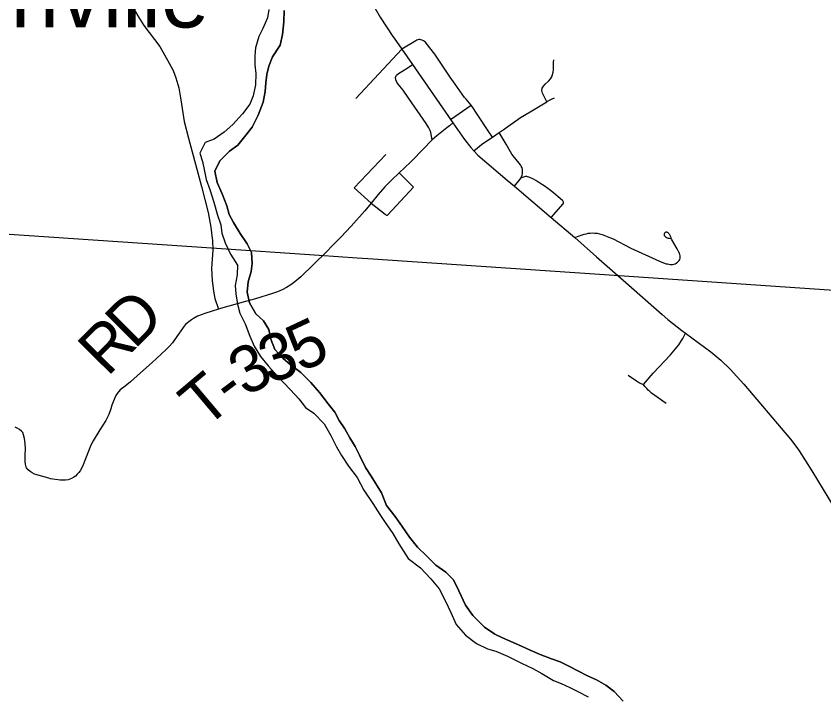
# Model space of a CAD drawing. Extents: x 0 to 34, y 0 to 22.
# Drawn here: x 6.535 to 7.513, y 18.32 to 19.145 of the extents above; entities that cross this region are included whole.
import ezdxf

# ---------------------------------------------------------------- set-up
doc = ezdxf.new("R2010")
doc.units = 0
for name, color, linetype in [('GM_X_County_Road', 7, 'Continuous'), ('GM_X_Major_River', 7, 'Continuous'), ('GM_X_Township_Road', 7, 'Continuous'), ('GM_X_Township_Road_Text', 7, 'Continuous'), ('GM_X_Township_Text', 7, 'Continuous'), ('GM_X_Unincorporated_Text', 7, 'Continuous')]:
    doc.layers.add(name, color=color, linetype=linetype)

msp = doc.modelspace()

# ---------------------------------------------------------------- linework, layer by layer
at = {"layer": 'GM_X_County_Road'}
for points in [[(6.9694, 19.15472), (6.97549, 19.14401), (6.99103, 19.1208), (6.99258, 19.11856), (7.0017, 19.10543), (7.01474, 19.08664), (7.05836, 19.02376), (7.06087, 19.02014), (7.06375, 19.016), (7.07784, 18.99571), (7.08547, 18.98599), (7.0892, 18.98208), (7.09397, 18.97708), (7.12928, 18.94671), (7.13819, 18.93917), (7.18278, 18.90145), (7.21134, 18.87729), (7.23782, 18.85362), (7.24754, 18.84506), (7.27322, 18.82243)], [(7.27322, 18.82243), (7.31724, 18.78362), (7.32407, 18.7776), (7.34126, 18.76436), (7.34544, 18.76127), (7.37628, 18.73848), (7.3883, 18.72855), (7.39951, 18.71769), (7.4162, 18.69918), (7.47264, 18.63286), (7.48028, 18.62268), (7.48321, 18.61849), (7.49872, 18.59416), (7.52584, 18.54883), (7.53463, 18.53611), (7.54442, 18.52416), (7.56365, 18.50395), (7.57609, 18.49101), (7.58953, 18.47705), (7.61443, 18.44873), (7.62015, 18.44201), (7.63038, 18.43057), (7.63847, 18.42135), (7.66073, 18.39596)]]:
    msp.add_lwpolyline(points, dxfattribs=at)
at = {"layer": 'GM_X_Major_River'}
for p, q in [((6.84059, 19.15339), (6.83917, 19.14315)), ((6.85888, 19.1384), (6.85914, 19.15242)), ((6.83917, 19.14315), (6.8336, 19.13059)), ((6.85712, 19.12322), (6.85888, 19.1384)), ((6.8336, 19.13059), (6.82839, 19.12069)), ((6.85459, 19.11032), (6.85712, 19.12322)), ((6.82839, 19.12069), (6.82472, 19.10701)), ((6.82472, 19.10701), (6.82367, 19.09753)), ((6.84525, 19.09621), (6.85459, 19.11032)), ((6.82367, 19.09753), (6.82377, 19.08654)), ((6.84081, 19.0848), (6.84525, 19.09621)), ((6.82377, 19.08654), (6.82499, 19.07594)), ((6.83825, 19.07455), (6.84081, 19.0848)), ((6.82499, 19.07594), (6.82436, 19.06229)), ((6.8372, 19.06468), (6.83825, 19.07455)), ((6.83616, 19.05406), (6.8372, 19.06468)), ((6.82436, 19.06229), (6.82183, 19.04863)), ((6.834, 19.04116), (6.83616, 19.05406)), ((6.82183, 19.04863), (6.81775, 19.03874)), ((6.81775, 19.03874), (6.80877, 19.02691)), ((6.82771, 19.02519), (6.834, 19.04116)), ((6.80877, 19.02691), (6.79716, 19.01392)), ((6.82064, 19.01072), (6.82771, 19.02519)), ((6.79716, 19.01392), (6.78664, 19.00473)), ((6.78664, 19.00473), (6.77461, 18.99628)), ((6.81278, 19.00118), (6.82064, 19.01072)), ((6.77461, 18.99628), (6.76367, 18.99239)), ((6.80305, 18.98896), (6.81278, 19.00118)), ((6.76367, 18.99239), (6.75697, 18.97945)), ((6.7929, 18.98167), (6.80305, 18.98896)), ((6.75697, 18.97945), (6.76047, 18.96925)), ((6.78127, 18.96982), (6.7929, 18.98167)), ((6.76047, 18.96925), (6.76284, 18.95752)), ((6.77532, 18.95764), (6.78127, 18.96982)), ((6.76284, 18.95752), (6.76482, 18.94731)), ((6.77809, 18.94364), (6.77532, 18.95764)), ((6.76482, 18.94731), (6.76909, 18.93522)), ((6.78427, 18.93006), (6.77809, 18.94364)), ((6.76909, 18.93522), (6.77414, 18.91973)), ((6.78969, 18.91533), (6.78427, 18.93006)), ((6.77414, 18.91973), (6.77844, 18.90423)), ((6.79281, 18.90512), (6.78969, 18.91533)), ((6.77844, 18.90423), (6.7827, 18.89253)), ((6.79781, 18.89531), (6.79281, 18.90512)), ((6.7827, 18.89253), (6.78393, 18.88231)), ((6.80587, 18.88213), (6.79781, 18.89531)), ((6.78393, 18.88231), (6.78781, 18.87059)), ((6.81431, 18.86932), (6.80587, 18.88213)), ((6.78781, 18.87059), (6.79436, 18.85701)), ((6.8197, 18.85876), (6.81431, 18.86932)), ((6.82057, 18.8455), (6.8197, 18.85876)), ((6.79436, 18.85701), (6.80281, 18.84345)), ((6.80281, 18.84345), (6.80215, 18.83169)), ((6.81914, 18.83602), (6.82057, 18.8455)), ((6.80215, 18.83169), (6.79999, 18.81879)), ((6.81584, 18.82348), (6.81914, 18.83602)), ((6.79999, 18.81879), (6.80084, 18.80894)), ((6.81444, 18.81096), (6.81584, 18.82348)), ((6.80084, 18.80894), (6.80284, 18.79646)), ((6.8172, 18.79772), (6.81444, 18.81096)), ((6.80284, 18.79646), (6.80558, 18.78549)), ((6.82489, 18.78453), (6.8172, 18.79772)), ((6.80558, 18.78549), (6.81213, 18.77229)), ((6.83442, 18.7759), (6.82489, 18.78453)), ((6.81213, 18.77229), (6.81755, 18.75756)), ((6.84056, 18.76573), (6.83442, 18.7759)), ((6.84293, 18.754), (6.84056, 18.76573)), ((6.81755, 18.75756), (6.82295, 18.74548)), ((6.84797, 18.74116), (6.84293, 18.754)), ((6.82295, 18.74548), (6.83063, 18.73267)), ((6.85752, 18.73064), (6.84797, 18.74116)), ((6.83063, 18.73267), (6.83981, 18.72138)), ((6.86704, 18.72277), (6.85752, 18.73064)), ((6.83981, 18.72138), (6.85127, 18.70898)), ((6.87961, 18.71341), (6.86704, 18.72277)), ((6.89145, 18.70139), (6.87961, 18.71341)), ((6.85127, 18.70898), (6.86693, 18.69245)), ((6.90214, 18.68936), (6.89145, 18.70139)), ((6.86693, 18.69245), (6.87686, 18.68155)), ((6.87686, 18.68155), (6.88528, 18.67102)), ((6.91248, 18.67544), (6.90214, 18.68936)), ((6.92052, 18.66528), (6.91248, 18.67544)), ((6.88528, 18.67102), (6.89517, 18.66429)), ((6.89517, 18.66429), (6.90777, 18.65114)), ((6.9259, 18.65547), (6.92052, 18.66528)), ((6.9328, 18.64531), (6.9259, 18.65547)), ((6.90777, 18.65114), (6.91584, 18.63719)), ((6.93895, 18.63437), (6.9328, 18.64531)), ((6.91584, 18.63719), (6.92277, 18.62324)), ((6.94509, 18.62382), (6.93895, 18.63437)), ((6.92277, 18.62324), (6.92892, 18.61268)), ((6.95048, 18.61326), (6.94509, 18.62382)), ((6.92892, 18.61268), (6.93736, 18.59987)), ((6.9578, 18.59817), (6.95048, 18.61326)), ((6.93736, 18.59987), (6.94769, 18.58633)), ((6.9647, 18.588), (6.9578, 18.59817)), ((6.94769, 18.58633), (6.95577, 18.57086)), ((6.97699, 18.56765), (6.9647, 18.588)), ((6.95577, 18.57086), (6.96688, 18.55467)), ((6.98318, 18.55217), (6.97699, 18.56765)), ((6.96688, 18.55467), (6.97532, 18.54148)), ((6.99389, 18.539), (6.98318, 18.55217)), ((6.97532, 18.54148), (6.98146, 18.53169)), ((7.00231, 18.52695), (6.99389, 18.539)), ((6.98146, 18.53169), (6.99104, 18.51813)), ((7.01113, 18.51377), (7.00231, 18.52695)), ((6.99104, 18.51813), (6.99834, 18.50569)), ((6.99834, 18.50569), (7.00946, 18.48799)), ((7.0207, 18.50173), (7.01113, 18.51377)), ((7.03176, 18.49122), (7.0207, 18.50173)), ((7.00946, 18.48799), (7.02432, 18.47675)), ((7.04321, 18.47996), (7.03176, 18.49122)), ((7.02432, 18.47675), (7.03692, 18.46323)), ((7.05501, 18.47135), (7.04321, 18.47996)), ((7.06455, 18.46234), (7.05501, 18.47135)), ((7.03692, 18.46323), (7.04687, 18.45119)), ((7.07072, 18.44875), (7.06455, 18.46234)), ((7.04687, 18.45119), (7.05456, 18.43648)), ((7.07882, 18.4314), (7.07072, 18.44875)), ((7.05456, 18.43648), (7.06111, 18.42252)), ((7.08801, 18.41898), (7.07882, 18.4314)), ((7.06111, 18.42252), (7.06767, 18.40818)), ((7.10213, 18.40471), (7.08801, 18.41898)), ((7.06767, 18.40818), (7.07914, 18.39502)), ((7.11431, 18.39648), (7.10213, 18.40471)), ((7.07914, 18.39502), (7.09209, 18.38491)), ((7.12381, 18.39202), (7.11431, 18.39648)), ((7.14661, 18.38162), (7.12381, 18.39202)), ((7.09209, 18.38491), (7.10577, 18.37859)), ((7.10577, 18.37859), (7.11563, 18.37565)), ((7.15724, 18.37679), (7.14661, 18.38162)), ((7.11563, 18.37565), (7.12968, 18.36971)), ((7.12968, 18.36971), (7.14678, 18.36115)), ((7.1694, 18.37159), (7.15724, 18.37679)), ((7.18306, 18.36641), (7.1694, 18.37159)), ((7.14678, 18.36115), (7.16046, 18.35484)), ((7.19369, 18.36272), (7.18306, 18.36641)), ((7.20433, 18.35751), (7.19369, 18.36272)), ((7.16046, 18.35484), (7.17149, 18.3485)), ((7.17149, 18.3485), (7.18556, 18.34029)), ((7.21573, 18.35155), (7.20433, 18.35751)), ((7.22675, 18.34597), (7.21573, 18.35155)), ((7.18556, 18.34029), (7.19505, 18.33658)), ((7.23777, 18.34076), (7.22675, 18.34597)), ((7.2488, 18.33442), (7.23777, 18.34076)), ((7.19505, 18.33658), (7.20531, 18.33175)), ((7.20531, 18.33175), (7.21519, 18.32692)), ((7.25908, 18.32694), (7.2488, 18.33442)), ((7.21519, 18.32692), (7.22773, 18.32021)), ((7.27016, 18.31491), (7.25908, 18.32694))]:
    msp.add_line(p, q, dxfattribs=at)
for points in [[(6.84059, 19.15339), (6.83917, 19.14315), (6.8336, 19.13059), (6.82839, 19.12069), (6.82472, 19.10701)], [(6.85914, 19.15242), (6.85888, 19.1384), (6.85712, 19.12322), (6.85459, 19.11032), (6.84525, 19.09621)], [(6.82472, 19.10701), (6.82367, 19.09753), (6.82377, 19.08654), (6.82499, 19.07594), (6.82436, 19.06229), (6.82183, 19.04863), (6.81775, 19.03874), (6.80877, 19.02691), (6.79716, 19.01392), (6.78664, 19.00473), (6.77461, 18.99628), (6.76367, 18.99239), (6.75697, 18.97945), (6.76047, 18.96925), (6.76284, 18.95752), (6.76482, 18.94731), (6.76909, 18.93522), (6.77414, 18.91973), (6.77844, 18.90423), (6.7827, 18.89253), (6.78393, 18.88231), (6.78781, 18.87059), (6.79436, 18.85701), (6.80281, 18.84345), (6.80215, 18.83169), (6.79999, 18.81879), (6.80084, 18.80894), (6.80284, 18.79646), (6.80558, 18.78549), (6.81213, 18.77229), (6.81755, 18.75756), (6.82295, 18.74548), (6.83063, 18.73267), (6.83981, 18.72138), (6.85127, 18.70898), (6.86693, 18.69245), (6.87686, 18.68155), (6.88528, 18.67102), (6.89517, 18.66429), (6.90777, 18.65114), (6.91584, 18.63719), (6.92277, 18.62324), (6.92892, 18.61268), (6.93736, 18.59987), (6.94769, 18.58633), (6.95577, 18.57086), (6.96688, 18.55467), (6.97532, 18.54148), (6.98146, 18.53169), (6.99104, 18.51813), (6.99834, 18.50569), (7.00946, 18.48799), (7.02432, 18.47675), (7.03692, 18.46323), (7.04687, 18.45119), (7.05456, 18.43648), (7.06111, 18.42252), (7.06767, 18.40818), (7.07914, 18.39502), (7.09209, 18.38491), (7.10577, 18.37859), (7.11563, 18.37565), (7.12968, 18.36971), (7.14678, 18.36115), (7.16046, 18.35484), (7.17149, 18.3485), (7.18556, 18.34029), (7.19505, 18.33658), (7.20531, 18.33175), (7.21519, 18.32692), (7.22773, 18.32021)], [(6.84525, 19.09621), (6.84081, 19.0848), (6.83825, 19.07455), (6.8372, 19.06468), (6.83616, 19.05406), (6.834, 19.04116), (6.82771, 19.02519), (6.82064, 19.01072), (6.81278, 19.00118), (6.80305, 18.98896), (6.7929, 18.98167), (6.78127, 18.96982), (6.77532, 18.95764), (6.77809, 18.94364), (6.78427, 18.93006), (6.78969, 18.91533), (6.79281, 18.90512), (6.79781, 18.89531), (6.80587, 18.88213), (6.81431, 18.86932), (6.8197, 18.85876), (6.82057, 18.8455), (6.81914, 18.83602), (6.81584, 18.82348), (6.81444, 18.81096), (6.8172, 18.79772), (6.82489, 18.78453), (6.83442, 18.7759), (6.84056, 18.76573), (6.84293, 18.754), (6.84797, 18.74116), (6.85752, 18.73064), (6.86704, 18.72277), (6.87961, 18.71341), (6.89145, 18.70139), (6.90214, 18.68936), (6.91248, 18.67544), (6.92052, 18.66528), (6.9259, 18.65547), (6.9328, 18.64531), (6.93895, 18.63437), (6.94509, 18.62382), (6.95048, 18.61326), (6.9578, 18.59817), (6.9647, 18.588), (6.97699, 18.56765), (6.98318, 18.55217), (6.99389, 18.539), (7.00231, 18.52695), (7.01113, 18.51377), (7.0207, 18.50173), (7.03176, 18.49122), (7.04321, 18.47996), (7.05501, 18.47135), (7.06455, 18.46234), (7.07072, 18.44875), (7.07882, 18.4314), (7.08801, 18.41898), (7.10213, 18.40471), (7.11431, 18.39648), (7.12381, 18.39202), (7.14661, 18.38162), (7.15724, 18.37679), (7.1694, 18.37159), (7.18306, 18.36641), (7.19369, 18.36272), (7.20433, 18.35751), (7.21573, 18.35155), (7.22675, 18.34597), (7.23777, 18.34076), (7.2488, 18.33442), (7.25908, 18.32694), (7.27016, 18.31491)]]:
    msp.add_lwpolyline(points, dxfattribs=at)
at = {"layer": 'GM_X_Township_Road'}
msp.add_line((6.94619, 19.04567), (7.0017, 19.10543), dxfattribs=at)
for points in [[(6.67288, 19.1615), (6.68334, 19.14355), (6.68943, 19.13395), (6.70879, 19.10862), (6.7201, 19.08832), (6.72459, 19.07933), (6.72806, 19.07056), (6.73144, 19.05869), (6.73414, 19.04415), (6.7383, 19.01763), (6.74322, 18.99746), (6.75925, 18.93889), (6.76721, 18.90738), (6.77061, 18.88963), (6.77219, 18.87572), (6.77238, 18.87401), (6.77273, 18.86161), (6.77135, 18.84002), (6.77214, 18.82454), (6.77279, 18.81886)], [(7.06087, 19.02014), (7.08581, 19.03735), (7.07984, 19.04464), (7.07769, 19.04692), (7.0664, 19.06294), (7.06049, 19.07126), (7.04169, 19.09935), (7.03143, 19.11258), (7.03037, 19.11369), (7.0292, 19.11471), (7.02787, 19.11559), (7.02634, 19.11624), (7.02483, 19.11669), (7.02354, 19.11688), (7.02227, 19.11692), (7.02111, 19.11669), (7.01997, 19.11619), (7.01864, 19.11549), (7.0017, 19.10543)], [(7.17732, 19.04146), (7.17208, 19.05209), (7.17142, 19.05506), (7.17189, 19.05801), (7.17347, 19.06059), (7.1755, 19.06284), (7.17988, 19.06703), (7.18183, 19.06931), (7.1834, 19.07188), (7.18456, 19.07464), (7.18525, 19.07756), (7.18549, 19.08055), (7.18561, 19.08958), (7.18583, 19.09259)], [(7.03875, 18.9956), (7.03685, 19.00429), (7.03596, 19.00674), (7.03438, 19.0099), (7.03118, 19.01515), (7.01034, 19.04569), (7.00329, 19.05576), (6.99748, 19.06294), (6.99573, 19.06548), (6.99445, 19.06821), (6.99421, 19.07114), (6.99531, 19.07398), (6.99764, 19.07597), (7.00816, 19.08238), (7.01065, 19.08399), (7.01474, 19.08664)], [(7.0892, 18.98208), (7.09358, 18.98569), (7.09835, 18.98963), (7.10598, 18.9949), (7.1117, 18.99885), (7.11977, 19.00447), (7.12449, 19.0077), (7.14552, 19.02238), (7.15725, 19.02942), (7.17732, 19.04146), (7.17845, 19.04215), (7.18391, 19.04503), (7.1867, 19.04634)], [(7.1117, 18.99885), (7.10728, 19.00527), (7.09302, 19.0266), (7.08715, 19.03584), (7.08581, 19.03735)], [(7.06375, 19.016), (7.0594, 19.01257), (7.0562, 19.01003), (7.04403, 19.00036), (7.03875, 18.9956), (7.02733, 18.98369), (7.01443, 18.97051)], [(7.13819, 18.93917), (7.14531, 18.94796), (7.14607, 18.94913), (7.14759, 18.95274), (7.14799, 18.95487), (7.1482, 18.95725), (7.14799, 18.95937), (7.14754, 18.96135), (7.14657, 18.96347), (7.14551, 18.96519), (7.14399, 18.96732), (7.13676, 18.97592), (7.13501, 18.97827), (7.13348, 18.9808), (7.12803, 18.99041), (7.11977, 19.00447)], [(6.96474, 18.91883), (6.94388, 18.93709), (6.98236, 18.97788)], [(7.01443, 18.97051), (7.01228, 18.96831), (6.99851, 18.9553), (6.99723, 18.95409), (6.99068, 18.94791)], [(6.96474, 18.91883), (6.98154, 18.90522), (6.98254, 18.90441), (6.98326, 18.90405), (6.98428, 18.90414), (6.98495, 18.90465), (7.01587, 18.93806), (6.99854, 18.95527)], [(6.99068, 18.94791), (6.98995, 18.94722), (6.98131, 18.93846), (6.97311, 18.92924), (6.96474, 18.91883), (6.95699, 18.90959), (6.94063, 18.89096), (6.92792, 18.87731), (6.91826, 18.86761)], [(7.18278, 18.90145), (7.19723, 18.91803), (7.19762, 18.91867), (7.19774, 18.91932), (7.19764, 18.91998), (7.19737, 18.92061), (7.19679, 18.92142), (7.19366, 18.9245), (7.19137, 18.9265), (7.18841, 18.92896), (7.18368, 18.93268), (7.17867, 18.93652), (7.17445, 18.93956), (7.16918, 18.94301), (7.16414, 18.94601), (7.16117, 18.94772), (7.15958, 18.94856), (7.15838, 18.94919), (7.15681, 18.94992), (7.15559, 18.95037), (7.15427, 18.9507), (7.15307, 18.95086), (7.1518, 18.95086), (7.15054, 18.95067), (7.14933, 18.95031), (7.14808, 18.94978), (7.14607, 18.94913)], [(7.21134, 18.87729), (7.22036, 18.88032), (7.22284, 18.88105), (7.22549, 18.88173), (7.22762, 18.88215), (7.22997, 18.88242), (7.233, 18.88258), (7.2356, 18.88254), (7.23846, 18.88229), (7.24141, 18.88165), (7.24465, 18.88062), (7.25461, 18.87679), (7.25782, 18.87537), (7.27945, 18.86416), (7.31399, 18.84829), (7.31867, 18.84644), (7.32215, 18.84536), (7.32362, 18.84497), (7.32528, 18.84462), (7.32675, 18.84443), (7.32816, 18.84434), (7.32971, 18.8444), (7.33122, 18.84457), (7.33298, 18.8452), (7.33438, 18.846), (7.33586, 18.84708), (7.33708, 18.84822), (7.33799, 18.8493), (7.33859, 18.85058), (7.33896, 18.85214), (7.33904, 18.85349), (7.33892, 18.85497), (7.33863, 18.85659), (7.3382, 18.85801), (7.33759, 18.85941), (7.33668, 18.86104), (7.33544, 18.86323), (7.32858, 18.87518), (7.32822, 18.87602), (7.32794, 18.87681), (7.32763, 18.87767), (7.32729, 18.87861), (7.32683, 18.87969), (7.3264, 18.88049), (7.3259, 18.88122), (7.32539, 18.88181), (7.32486, 18.88237), (7.324, 18.88303), (7.32335, 18.88327), (7.32278, 18.88342), (7.32169, 18.88344), (7.3207, 18.88301), (7.32006, 18.88237), (7.31971, 18.88163), (7.31958, 18.88061), (7.31981, 18.87964), (7.32028, 18.87885), (7.32109, 18.87798), (7.32207, 18.87734), (7.32339, 18.87677), (7.32467, 18.87641), (7.32624, 18.87619), (7.3277, 18.87605)], [(6.91826, 18.86761), (6.91757, 18.86691), (6.91043, 18.85972), (6.87927, 18.82949), (6.87225, 18.8234), (6.86728, 18.81975), (6.86214, 18.81656), (6.8567, 18.8137)], [(6.77279, 18.81886), (6.77355, 18.81223), (6.7754, 18.80315), (6.77951, 18.79009)], [(6.8567, 18.8137), (6.85104, 18.81121), (6.8452, 18.80909), (6.82443, 18.80285), (6.81236, 18.79948), (6.78217, 18.79085), (6.77951, 18.79009), (6.77212, 18.78798), (6.76311, 18.78503), (6.75426, 18.78158), (6.74944, 18.77904), (6.74687, 18.77737), (6.74207, 18.77359), (6.73987, 18.77147), (6.7378, 18.76921), (6.73589, 18.76677), (6.72933, 18.75704), (6.72394, 18.74957), (6.7199, 18.74493), (6.71558, 18.74055), (6.71091, 18.73662), (6.70419, 18.73015), (6.69986, 18.72597), (6.69572, 18.72229), (6.68513, 18.71312), (6.67293, 18.70227), (6.66671, 18.69709), (6.66067, 18.69226), (6.65698, 18.68786), (6.65549, 18.68545), (6.6542, 18.68271), (6.65066, 18.67387), (6.6491, 18.66942), (6.64682, 18.66243), (6.64317, 18.65524), (6.63586, 18.64383), (6.62766, 18.63057), (6.62489, 18.62526), (6.61945, 18.61068), (6.61485, 18.59956), (6.61201, 18.59421), (6.61065, 18.59229), (6.60862, 18.5901), (6.60629, 18.58789), (6.60444, 18.58643), (6.60164, 18.58506), (6.59744, 18.58356), (6.59416, 18.58305), (6.59108, 18.5828), (6.58803, 18.58283), (6.57631, 18.58468), (6.57407, 18.58521), (6.55955, 18.58934), (6.55671, 18.59036), (6.55394, 18.59173), (6.55133, 18.59332), (6.54908, 18.59541), (6.54711, 18.59795), (6.54655, 18.59908), (6.54572, 18.60218), (6.54534, 18.60528), (6.5453, 18.60843), (6.54561, 18.61379), (6.54583, 18.62056), (6.5455, 18.62744), (6.54472, 18.63331), (6.54347, 18.63788), (6.54247, 18.64057), (6.54107, 18.64253), (6.53864, 18.64451), (6.53596, 18.64604), (6.53321, 18.64734)], [(7.32204, 18.67582), (7.30448, 18.68855), (7.30214, 18.69041), (7.30023, 18.69207), (7.29857, 18.69391), (7.29739, 18.69533), (7.29639, 18.69664), (7.29471, 18.69886), (7.30618, 18.71256), (7.32748, 18.73502), (7.33358, 18.74201), (7.33734, 18.74692), (7.34066, 18.75213), (7.34209, 18.75487), (7.34544, 18.76127)], [(7.2759, 18.71041), (7.28601, 18.70322), (7.28981, 18.70085), (7.29138, 18.70003), (7.29471, 18.69886)]]:
    msp.add_lwpolyline(points, dxfattribs=at)
at = {"layer": 'GM_X_Township_Text'}
msp.add_lwpolyline([(8.7763, 18.73648), (7.71162, 18.8006), (7.68511, 18.80199), (7.26526, 18.83047), (6.96075, 18.85112), (6.94772, 18.85201), (6.90184, 18.85512), (6.77132, 18.86397), (6.34691, 18.89276), (5.47662, 18.95179), (4.31246, 19.03076), (4.29728, 19.03179), (4.1694, 19.04046), (3.38331, 19.09378), (3.27141, 17.36706), (3.22787, 16.69522), (3.18216, 15.98984), (3.16074, 15.6594), (3.11017, 14.87895), (3.06817, 14.23092), (3.06652, 14.20544)], dxfattribs=at)

# ---------------------------------------------------------------- texts
at = {"layer": 'GM_X_Township_Road_Text'}
for s, rotation, p in [('D', 44.86347, (6.67774, 18.7405)), ('5', 25.0576, (6.87929, 18.71318)), ('R', 45.356, (6.64504, 18.70738)), ('3', 19.52779, (6.84077, 18.69921)), ('3', 27.86372, (6.81183, 18.68373)), ('T', 40.14576, (6.7633, 18.64418)), ('-', 36.70752, (6.79508, 18.67102))]:
    msp.add_text(s, height=0.05682, rotation=rotation, dxfattribs=at).set_placement(p)
at = {"layer": 'GM_X_Unincorporated_Text'}
msp.add_text('Haydenville', height=0.0789773, rotation=0.00001, dxfattribs=at).set_placement((6.2226, 19.13164))

doc.saveas('drawing.dxf')
